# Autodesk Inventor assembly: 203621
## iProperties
Created: 2008-01
Part Number: 203621
Document SubType Name: Assembly
Designer: jjohnson
Mass: 26.128 g
Surface Area: 46.9717 cm^2
Volume: 6.69373 cm^3
Density: 3.90335 g/cm^3
Author: jjohnson
